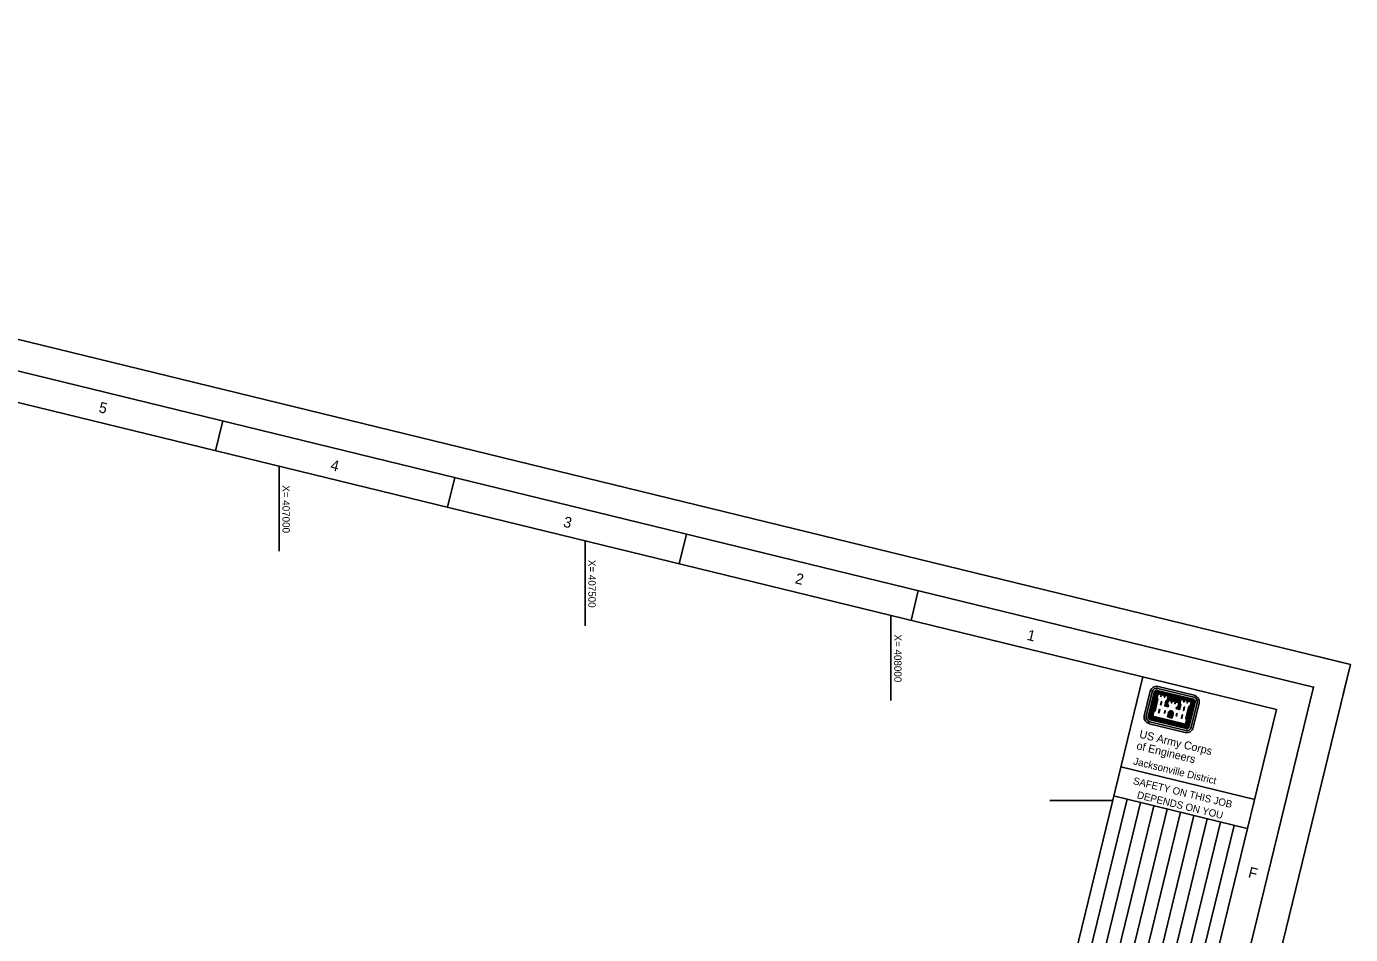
# Model space of a CAD drawing. Extents: x 403671 to 408751, y 1189919 to 1194265.
# Drawn here: x 406587 to 408751, y 1192781 to 1194265 of the extents above; entities that cross this region are included whole.
import ezdxf

# ---------------------------------------------------------------- set-up
doc = ezdxf.new("R2010")
doc.units = 0
for name, color, linetype in [('G-ANNO-NPLT', 7, 'Continuous'), ('G-ANNO-TEXT-LOGO', 7, 'Continuous'), ('G-ANNO-TEXT-TTLB', 7, 'Continuous'), ('G-ANNO-TTLB', 7, 'Continuous'), ('V-TOPO-COOR-STAT', 7, 'Continuous')]:
    doc.layers.add(name, color=color, linetype=linetype)

msp = doc.modelspace()

# ---------------------------------------------------------------- linework, layer by layer
at = {"layer": 'G-ANNO-NPLT'}
msp.add_lwpolyline([(404476.5, 1194264.7), (408751.2, 1193222.2), (407945.6, 1189919), (403670.9, 1190961.5)], close=True, dxfattribs=at)
msp.add_lwpolyline([(408739.3, 1193173.6), (408751.2, 1193222.2), (408702.6, 1193234)], dxfattribs=at)
at = {"layer": 'G-ANNO-TEXT-LOGO'}
for p, q in [((408423.8, 1193178.4), (408414.1, 1193138.6)), ((408417.2, 1193137.8), (408426.9, 1193177.6)), ((408430.3, 1193176.8), (408420.6, 1193137)), ((408431.2, 1193176.6), (408421.5, 1193136.8)), ((408432, 1193176.4), (408422.3, 1193136.6)), ((408432.9, 1193176.2), (408423.1, 1193136.4)), ((408433.7, 1193176), (408424, 1193136.1)), ((408434.6, 1193175.8), (408425, 1193136.2)), ((408435.4, 1193175.6), (408426, 1193136.9)), ((408493.4, 1193162), (408434.4, 1193176.4)), ((408493.6, 1193162.9), (408434.6, 1193177.3)), ((408493.8, 1193163.7), (408434.8, 1193178.1)), ((408494, 1193164.6), (408435, 1193179)), ((408494.3, 1193165.4), (408435.2, 1193179.8)), ((408436, 1193183.1), (408495.1, 1193168.7)), ((408495.8, 1193171.9), (408436.8, 1193186.3)), ((408434, 1193167), (408429, 1193146.6)), ((408434.7, 1193165.9), (408430.1, 1193147.3)), ((408453.4, 1193165.6), (408471.5, 1193161.2)), ((408453.7, 1193166.5), (408471.7, 1193162.1)), ((408453.8, 1193167.3), (408471.9, 1193162.9)), ((408454.1, 1193168.1), (408472.1, 1193163.7)), ((408454.3, 1193169), (408472.3, 1193164.6)), ((408454.5, 1193169.8), (408472.5, 1193165.4)), ((408454.7, 1193170.7), (408472.7, 1193166.3)), ((408492.1, 1193161.7), (408482.7, 1193123.1)), ((408492.9, 1193161.6), (408483.3, 1193122)), ((408488.3, 1193152.8), (408483.8, 1193134.2)), ((408493.8, 1193161.3), (408484.1, 1193121.5)), ((408489.4, 1193153.4), (408484.4, 1193133.2)), ((408494.6, 1193161.1), (408484.9, 1193121.3)), ((408495.4, 1193160.9), (408485.7, 1193121.1)), ((408496.3, 1193160.7), (408486.6, 1193120.9)), ((408497.2, 1193160.5), (408487.5, 1193120.7)), ((408500.5, 1193159.7), (408490.8, 1193119.9)), ((408494, 1193119.1), (408503.7, 1193158.9)), ((408482.6, 1193117.7), (408423.6, 1193132.1)), ((408482.8, 1193118.5), (408423.7, 1193132.9)), ((408483, 1193119.4), (408424, 1193133.8)), ((408483.2, 1193120.3), (408424.2, 1193134.7)), ((408483.4, 1193121), (408424.4, 1193135.4)), ((408483.3, 1193122), (408425, 1193136.2)), ((408482.7, 1193123.1), (408426, 1193136.9)), ((408451.8, 1193136.7), (408453.4, 1193143.2)), ((408451.8, 1193136.7), (408459.6, 1193134.8)), ((408452.6, 1193136.5), (408454.2, 1193143)), ((408453.5, 1193136.3), (408455.1, 1193142.8)), ((408454.4, 1193136.1), (408455.9, 1193142.6)), ((408455.1, 1193135.9), (408456.7, 1193142.4)), ((408456.3, 1193135.6), (408457.9, 1193142.1)), ((408457.1, 1193135.4), (408458.7, 1193141.9)), ((408458, 1193135.2), (408459.5, 1193141.7)), ((408458.8, 1193135), (408460.4, 1193141.5)), ((408459.6, 1193134.8), (408461.2, 1193141.3)), ((408421.9, 1193125.5), (408481, 1193111.1)), ((408481.8, 1193114.3), (408422.7, 1193128.7))]:
    msp.add_line(p, q, dxfattribs=at)
for points in [[(408436.1, 1193175.4), (408434.2, 1193167.7), (408435.4, 1193165.7), (408430.9, 1193147.1), (408428.8, 1193145.8), (408426.8, 1193137.3), (408482.2, 1193123.8), (408484.2, 1193132.3), (408482.9, 1193134.5), (408487.4, 1193153), (408489.6, 1193154.2), (408491.4, 1193161.9), (408484.2, 1193163.7), (408478.5, 1193165.1), (408473.3, 1193166.3), (408471.4, 1193158.7), (408472.8, 1193156.6), (408471.2, 1193149.8), (408467.1, 1193150.8), (408467.3, 1193151.4), (408469.4, 1193152.8), (408471.3, 1193160.3), (408464, 1193162.1), (408458.4, 1193163.5), (408453.2, 1193164.7), (408451.4, 1193157.2), (408452.7, 1193155), (408452.5, 1193154.3), (408448.5, 1193155.3), (408450.1, 1193162.1), (408452.3, 1193163.3), (408454.1, 1193171), (408446.8, 1193172.8), (408441.2, 1193174.2), (408436.1, 1193175.4)], [(408436.6, 1193174.3), (408435.1, 1193167.9), (408436.4, 1193165.8), (408431.7, 1193146.5), (408429.5, 1193145.2), (408427.8, 1193138), (408481.6, 1193124.9), (408483.3, 1193132.1), (408481.9, 1193134.3), (408486.6, 1193153.5), (408488.9, 1193154.8), (408490.5, 1193161.2), (408485.2, 1193162.5), (408484.5, 1193159.5), (408484, 1193159.6), (408484.7, 1193162.6), (408479.6, 1193163.9), (408478.8, 1193160.9), (408478.4, 1193161), (408479.2, 1193164), (408473.9, 1193165.3), (408472.4, 1193158.8), (408473.7, 1193156.7), (408471.8, 1193148.8), (408466.1, 1193150.2), (408466.6, 1193152), (408468.8, 1193153.3), (408470.3, 1193159.7), (408465.1, 1193161), (408464.3, 1193158), (408464, 1193158.1), (408464.7, 1193161.1), (408459.4, 1193162.4), (408458.7, 1193159.4), (408458.2, 1193159.5), (408459, 1193162.5), (408453.8, 1193163.8), (408452.2, 1193157.4), (408453.6, 1193155.2), (408453.1, 1193153.3), (408447.5, 1193154.7), (408449.4, 1193162.6), (408451.6, 1193163.9), (408453.1, 1193170.3), (408448, 1193171.6), (408447.3, 1193168.6), (408446.8, 1193168.7), (408447.5, 1193171.7), (408442.3, 1193173), (408441.5, 1193170), (408441.1, 1193170.1), (408441.9, 1193173.1), (408436.6, 1193174.3)], [(408442.1, 1193162), (408440.7, 1193156.4), (408441.3, 1193156.2), (408442.6, 1193161.9), (408442.1, 1193162)], [(408451.5, 1193161.9), (408450.9, 1193161.5), (408449.5, 1193156), (408451.4, 1193155.5), (408450.4, 1193157.1), (408451.6, 1193161.9)], [(408471.5, 1193157), (408471.9, 1193156.4), (408470.5, 1193150.8), (408468.8, 1193151.3), (408470.3, 1193152.3), (408471.4, 1193157.1)], [(408479.9, 1193152.8), (408478.5, 1193147.2), (408478, 1193147.3), (408479.4, 1193152.9), (408479.9, 1193152.8)], [(408438.9, 1193149.1), (408437.5, 1193143.4), (408438.1, 1193143.2), (408439.5, 1193148.9), (408438.9, 1193149.1)], [(408447.8, 1193146.9), (408446.9, 1193142.9), (408447.4, 1193142.8), (408448.3, 1193146.8), (408447.8, 1193146.9)], [(408467.9, 1193142), (408466.9, 1193138), (408466.4, 1193138.2), (408467.4, 1193142.1), (408467.9, 1193142)], [(408476.7, 1193139.9), (408475.3, 1193134.1), (408474.8, 1193134.3), (408476.2, 1193140), (408476.7, 1193139.9)]]:
    msp.add_lwpolyline(points, dxfattribs=at)
for centre, major_axis, start_param, end_param in [((408434.2, 1193175.9), (10.4, -2.5), 1.57078, 3.141576), ((408434.2, 1193175.9), (7.28, -1.77), 1.57078, 3.141576), ((408434.2, 1193175.9), (3.9, -0.95), 1.57078, 3.141576), ((408434.2, 1193175.9), (3.06, -0.75), 1.57078, 3.141576), ((408434.2, 1193175.9), (2.22, -0.54), 1.57078, 3.141576), ((408434.2, 1193175.9), (1.37, -0.33), 1.57078, 3.141576), ((408434.2, 1193175.9), (0.53, -0.129), 1.57078, 3.141576), ((408493.2, 1193161.5), (0.53, -0.129), 6.283169, 7.853965), ((408493.2, 1193161.5), (1.37, -0.33), 6.283169, 7.853965), ((408493.2, 1193161.5), (2.22, -0.54), 6.283169, 7.853965), ((408493.2, 1193161.5), (3.06, -0.75), 6.283169, 7.853965), ((408493.2, 1193161.5), (3.9, -0.95), 6.283169, 7.853965), ((408493.2, 1193161.5), (7.28, -1.77), 6.28317, 7.853966), ((408493.2, 1193161.5), (10.4, -2.5), 6.283169, 7.853965), ((408424.5, 1193136), (-10.4, 2.5), 6.28317, 7.853966), ((408424.5, 1193136), (-7.28, 1.77), 6.28317, 7.853966), ((408424.5, 1193136), (-3.9, 0.95), 6.28317, 7.853966), ((408424.5, 1193136), (-3.06, 0.75), 6.28317, 7.853966), ((408424.5, 1193136), (-2.22, 0.54), 6.28317, 7.853966), ((408424.5, 1193136), (-1.37, 0.33), 6.28317, 7.853966), ((408424.5, 1193136), (-0.53, 0.129), 6.28317, 7.853966), ((408458.6, 1193141.5), (-5.4, 1.32), 4.985832, 6.214359), ((408458.6, 1193141.5), (-4.55, 1.11), 4.947465, 6.21436), ((408458.6, 1193141.5), (-3.71, 0.9), 4.947465, 6.21436), ((408458.6, 1193141.5), (-2.87, 0.7), 4.947465, 6.21436), ((408455.7, 1193142.2), (2.02, -0.49), 0.068794, 1.335689), ((408458.6, 1193141.5), (-2.02, 0.49), 4.947465, 6.214359), ((408455.7, 1193142.2), (2.87, -0.7), 0.068794, 1.335689), ((408455.7, 1193142.2), (3.71, -0.9), 0.068795, 1.335689), ((408455.7, 1193142.2), (4.55, -1.11), 0.068795, 1.335689), ((408455.7, 1193142.2), (5.4, -1.32), 0.068795, 1.29842), ((408483.5, 1193121.6), (10.4, -2.5), 4.712373, 6.28317), ((408483.5, 1193121.6), (-7.28, 1.77), 1.570781, 3.141577), ((408483.5, 1193121.6), (3.9, -0.95), 4.712373, 6.28317), ((408483.5, 1193121.6), (3.06, -0.75), 4.712373, 6.28317), ((408483.5, 1193121.6), (2.22, -0.54), 4.712373, 6.28317), ((408483.5, 1193121.6), (1.37, -0.33), 4.712373, 6.28317), ((408483.5, 1193121.6), (0.53, -0.129), 4.712373, 6.28317)]:
    msp.add_ellipse(centre, major_axis=major_axis, ratio=0.99964, start_param=start_param, end_param=end_param, dxfattribs=at)
at = {"layer": 'G-ANNO-TTLB'}
for p, q in [((406908, 1193620.2), (406896.1, 1193571.6)), ((407286.9, 1193527.8), (407275, 1193479.2)), ((407665.8, 1193435.4), (407653.9, 1193386.8)), ((408044.7, 1193343), (408032.8, 1193294.4)), ((408411.7, 1193202), (407653.5, 1190093.2)), ((408375.9, 1193055.1), (408594.5, 1193001.8)), ((408385.9, 1193002.1), (408187.4, 1192188)), ((408363.6, 1193007.5), (408582.2, 1192954.2)), ((408407.8, 1192996.8), (408209.3, 1192182.7)), ((408429.6, 1192991.4), (408231.1, 1192177.4)), ((408451.5, 1192986.1), (408253, 1192172)), ((408473.4, 1192980.8), (408274.8, 1192166.7)), ((408495.2, 1192975.4), (408296.7, 1192161.4)), ((408517.1, 1192970.1), (408318.5, 1192156.1)), ((408538.9, 1192964.8), (408340.4, 1192150.7)), ((408560.8, 1192959.4), (408362.3, 1192145.4))]:
    msp.add_line(p, q, dxfattribs=at)
for points in [[(403731.3, 1190998.2), (407908.9, 1189979.4), (408690.7, 1193185.4), (404513.2, 1194204.2)], [(408630.3, 1193148.7), (404622.8, 1194126), (403864.6, 1191017.2), (407872.1, 1190039.9)]]:
    msp.add_lwpolyline(points, close=True, dxfattribs=at)
at = {"layer": 'V-TOPO-COOR-STAT'}
for p, q in [((407000, 1193407.4), (407000, 1193546.3)), ((407500, 1193285.4), (407500, 1193424.4)), ((408000, 1193163.5), (408000, 1193302.4)), ((408259.5, 1193000), (408362.4, 1193000))]:
    msp.add_line(p, q, dxfattribs=at)

# ---------------------------------------------------------------- texts
at = {"layer": 'G-ANNO-TEXT-TTLB'}
for s, height, p in [('US Army Corps', 13.086, (408405, 1193102.8)), ('of Engineers', 13.086, (408400.4, 1193084)), ('Jacksonville District', 11.9, (408395.4, 1193059.1)), ('SAFETY ON THIS JOB', 11.9, (408394.8, 1193027)), ('DEPENDS ON YOU', 11.9, (408401.3, 1193003.9))]:
    msp.add_text(s, height=height, rotation=346.2946, dxfattribs=at).set_placement(p)
at = {"layer": 'G-ANNO-TTLB'}
for s, p in [('5', (406703.9, 1193634.7)), ('4', (407082.7, 1193540.4)), ('3', (407463.3, 1193447.6)), ('2', (407842.2, 1193355.2)), ('1', (408221.1, 1193262.8)), ('F', (408582.8, 1192874.8))]:
    msp.add_text(s, height=17.5, rotation=346.2946, dxfattribs=at).set_placement(p)
at = {"layer": 'V-TOPO-COOR-STAT'}
for s, p in [('X= 407000', (407005.3, 1193515.1)), ('X= 407500', (407505.3, 1193393.2)), ('X= 408000', (408005.3, 1193271.3))]:
    msp.add_text(s, height=12, rotation=270, dxfattribs=at).set_placement(p)

doc.saveas('drawing.dxf')
